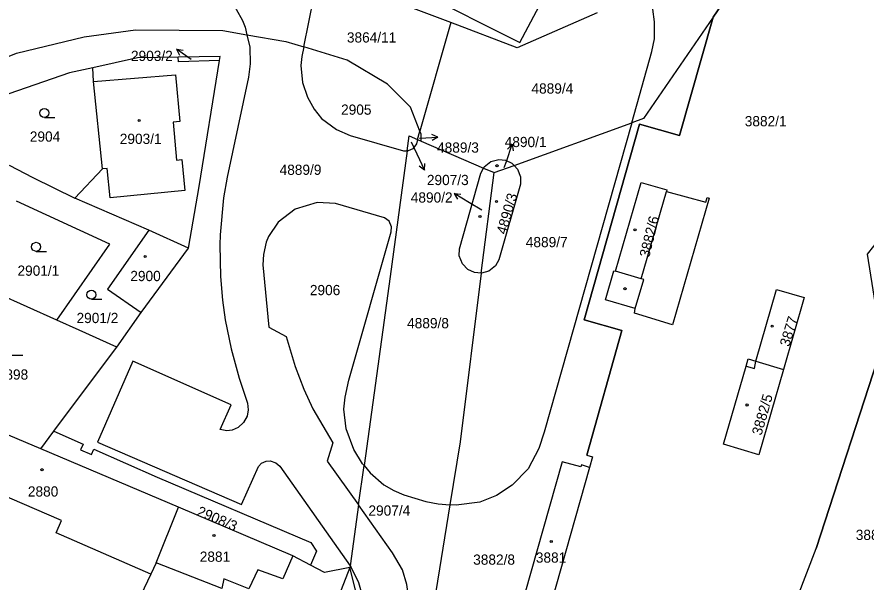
# Model space of a CAD drawing. Extents: x -527335 to -526256, y -1079142 to -1077836.
# Drawn here: x -526891.4 to -526750.1, y -1078714.2 to -1078620.2 of the extents above; entities that cross this region are included whole.
import ezdxf

# ---------------------------------------------------------------- set-up
doc = ezdxf.new("R2010")
doc.units = 0
for name, color, linetype in [('Hranice parcel', 7, 'Continuous'), ('Parcelní čísla', 7, 'Continuous'), ('Pop  PČ popisy', 7, 'Continuous'), ('Vnitřní kresba', 7, 'Continuous'), ('Vrstva 54', 7, 'Continuous'), ('Značky budov', 7, 'Continuous'), ('Značky kultur', 7, 'Continuous')]:
    doc.layers.add(name, color=color, linetype=linetype)

msp = doc.modelspace()

# ---------------------------------------------------------------- linework, layer by layer
at = {"layer": 'Hranice parcel'}
for p, q in [((-526843.73, -1078625.21), (-526841.41, -1078613.96)), ((-526819.27, -1078621.16), (-526824.4, -1078639.2)), ((-526808.76, -1078644.91), (-526789.19, -1078637.84)), ((-526824.79, -1078640.59), (-526824.4, -1078639.2)), ((-526824.79, -1078640.59), (-526824.19, -1078640.85)), ((-526824.19, -1078640.85), (-526813.82, -1078645.35)), ((-526813.82, -1078645.35), (-526812.08, -1078646.11)), ((-526812.08, -1078646.11), (-526808.76, -1078644.91)), ((-526814.2, -1078662.85), (-526812.08, -1078646.11)), ((-526869.47, -1078655.69), (-526881.81, -1078650.35)), ((-526862.92, -1078658.65), (-526869.47, -1078655.69)), ((-526870.77, -1078669.37), (-526862.92, -1078658.65)), ((-526884.81, -1078670.65), (-526900.22, -1078663.69)), ((-526874.82, -1078675.16), (-526870.77, -1078669.37)), ((-526768.55, -1078677.49), (-526763.94, -1078678.83)), ((-526887.47, -1078692.06), (-526885.27, -1078689.12)), ((-526864.56, -1078701.77), (-526887.47, -1078692.06)), ((-526834.61, -1078701.38), (-526833.7, -1078694.84)), ((-526796.21, -1078695.13), (-526804.6, -1078724.76)), ((-526868.26, -1078711.02), (-526864.56, -1078701.77)), ((-526845.53, -1078709.84), (-526864.56, -1078701.77)), ((-526834.61, -1078701.38), (-526836.01, -1078711.53)), ((-526819.43, -1078701.36), (-526822.95, -1078723.3)), ((-526842.59, -1078711.4), (-526845.53, -1078709.84)), ((-526836.05, -1078711.79), (-526839.19, -1078719.76)), ((-526836.01, -1078711.53), (-526836.05, -1078711.79)), ((-526833.99, -1078719.88), (-526836.05, -1078711.79))]:
    msp.add_line(p, q, dxfattribs=at)
for points in [[(-526766.12, -1078610.17), (-526769.16, -1078610.73), (-526775.66, -1078620.23)], [(-526869.37, -1078612.14), (-526867.13, -1078612.03), (-526863.95, -1078612.46), (-526860.92, -1078613.57), (-526858.13, -1078615.36), (-526857.06, -1078616.32), (-526854.94, -1078618.9), (-526853.89, -1078620.81), (-526853.48, -1078621.91), (-526853.17, -1078623.18)], [(-526789.19, -1078637.84), (-526785.84, -1078625.99), (-526785.42, -1078623.83), (-526785.41, -1078621.01), (-526785.67, -1078618.95), (-526786.3, -1078616.83), (-526788.13, -1078613.38), (-526789.05, -1078612.35)], [(-526819.27, -1078621.16), (-526833.71, -1078615.66), (-526841.41, -1078613.96)], [(-526824.79, -1078615.85), (-526807.79, -1078624.46), (-526803.66, -1078616.58)], [(-526794.91, -1078619.55), (-526808.25, -1078625.35), (-526819.27, -1078621.16)], [(-526775.66, -1078620.23), (-526781.26, -1078639.92), (-526787.88, -1078638.05), (-526797.07, -1078670.6), (-526790.82, -1078672.37), (-526796.68, -1078693.11), (-526795.72, -1078693.38), (-526796.21, -1078695.13)], [(-526775.66, -1078620.23), (-526787.22, -1078637.13), (-526789.19, -1078637.84)], [(-526921.59, -1078644.68), (-526904.95, -1078631.71), (-526891.51, -1078626.22), (-526880.24, -1078623.51), (-526871.73, -1078622.35), (-526857.21, -1078622.49), (-526853.17, -1078623.18)], [(-526853.17, -1078623.18), (-526852.68, -1078625.23), (-526852.63, -1078628.02), (-526852.92, -1078630.22), (-526856.44, -1078646.89), (-526857.06, -1078650.28), (-526857.65, -1078656.43), (-526857.7, -1078658.13), (-526857.58, -1078663.37), (-526857.25, -1078667.34), (-526856.78, -1078670.59), (-526855.82, -1078675.44), (-526854.48, -1078680.3), (-526853.09, -1078684.47), (-526852.97, -1078685.55), (-526853.14, -1078686.59), (-526853.72, -1078687.66), (-526854.66, -1078688.48), (-526855.62, -1078688.92), (-526856.53, -1078689.06), (-526857.64, -1078688.84), (-526855.82, -1078684.74), (-526872.17, -1078677.46), (-526878.01, -1078690.91), (-526854.06, -1078701.28), (-526851.27, -1078695), (-526850.77, -1078694.45), (-526849.95, -1078694.09), (-526849.31, -1078694.04), (-526848.37, -1078694.36), (-526847.72, -1078694.95), (-526836.01, -1078711.53)], [(-526853.17, -1078623.18), (-526846.72, -1078624.29), (-526843.73, -1078625.21)], [(-526843.73, -1078625.21), (-526844.05, -1078626.78), (-526844.2, -1078628.27), (-526843.91, -1078631.11), (-526843.13, -1078633.56), (-526842.02, -1078635.55), (-526840.76, -1078637.11), (-526838.3, -1078638.92), (-526836.02, -1078639.96), (-526827.16, -1078642.46), (-526826.53, -1078642.46)], [(-526824.4, -1078639.2), (-526825.96, -1078635.22), (-526829.78, -1078631.37), (-526836.5, -1078627.43), (-526843.73, -1078625.21)], [(-526864.61, -1078626.91), (-526871.37, -1078627.02), (-526878.81, -1078628.66)], [(-526857.75, -1078627.47), (-526857.64, -1078626.79), (-526864.61, -1078626.91)], [(-526857.75, -1078627.47), (-526864.55, -1078627.7), (-526864.61, -1078626.91)], [(-526878.81, -1078628.66), (-526882.67, -1078629.51), (-526901.46, -1078636.01), (-526901.58, -1078636.57)], [(-526881.81, -1078650.35), (-526877.21, -1078645.49), (-526878.67, -1078630.96), (-526878.81, -1078628.66)], [(-526862.92, -1078658.65), (-526861.14, -1078648.4), (-526857.75, -1078627.47)], [(-526789.19, -1078637.84), (-526803.74, -1078689.27), (-526804.63, -1078692.01), (-526806.42, -1078695.38), (-526809.08, -1078698.09), (-526811.68, -1078699.8), (-526814.45, -1078700.92), (-526818.39, -1078701.44), (-526819.43, -1078701.36)], [(-526826.53, -1078642.46), (-526826.2, -1078639.98), (-526824.79, -1078640.59)], [(-526824.19, -1078640.85), (-526824.2, -1078639.7), (-526824.4, -1078639.2)], [(-526824.79, -1078640.59), (-526825, -1078641.33), (-526825.59, -1078642.15), (-526826.34, -1078642.46), (-526826.53, -1078642.46)], [(-526826.53, -1078642.46), (-526829.34, -1078663.37), (-526833.7, -1078694.84)], [(-526813.82, -1078645.35), (-526813.7, -1078645.14), (-526812.63, -1078644.28), (-526811.27, -1078643.9), (-526810.18, -1078644.02), (-526809.12, -1078644.53), (-526808.76, -1078644.91)], [(-526892.72, -1078644.86), (-526888.78, -1078646.91), (-526881.81, -1078650.35)], [(-526814.2, -1078662.85), (-526815.36, -1078662.74), (-526816.43, -1078662.24), (-526817.34, -1078661.29), (-526817.86, -1078659.97), (-526817.84, -1078658.8), (-526814.29, -1078646.19), (-526813.82, -1078645.35)], [(-526808.76, -1078644.91), (-526808.17, -1078645.52), (-526807.69, -1078646.82), (-526807.7, -1078648.01), (-526811.28, -1078660.61), (-526811.85, -1078661.63), (-526812.94, -1078662.52), (-526814.17, -1078662.85), (-526814.2, -1078662.85)], [(-526788.7, -1078669.48), (-526788.59, -1078668.73), (-526793.57, -1078667.29), (-526792.14, -1078662.45), (-526791.9, -1078662.52), (-526787.63, -1078647.77), (-526783.36, -1078648.99), (-526783.43, -1078649.22), (-526776.87, -1078651.04), (-526776.62, -1078650.25), (-526776.3, -1078650.36), (-526782.4, -1078671.44), (-526788.7, -1078669.48)], [(-526884.81, -1078670.65), (-526875.97, -1078658.01), (-526891.48, -1078650.84)], [(-526833.7, -1078694.84), (-526833.97, -1078694.53), (-526835.42, -1078692.18), (-526836.66, -1078688.74), (-526837.04, -1078685.43), (-526836.83, -1078683.47), (-526836.21, -1078680.65), (-526829.17, -1078655.93), (-526829.11, -1078655.11), (-526829.53, -1078654.17), (-526830.32, -1078653.6), (-526838.47, -1078651.25), (-526841.47, -1078651.1), (-526845.15, -1078652.19), (-526847.97, -1078654.37), (-526849.57, -1078656.72), (-526849.98, -1078657.67), (-526850.44, -1078659.71), (-526850.52, -1078661.43), (-526849.51, -1078671.82), (-526846.64, -1078673.34), (-526845.17, -1078678.38), (-526843.73, -1078682.14), (-526842.22, -1078685.38), (-526838.87, -1078691.04), (-526839.82, -1078694.07), (-526834.61, -1078701.38)], [(-526869.47, -1078655.69), (-526876.34, -1078665.47), (-526870.77, -1078669.37)], [(-526814.2, -1078662.85), (-526817.74, -1078690.87), (-526819.43, -1078701.36)], [(-526768.55, -1078677.49), (-526765.14, -1078665.52), (-526760.53, -1078666.85), (-526763.94, -1078678.83)], [(-526874.82, -1078675.16), (-526881.1, -1078672.32), (-526884.81, -1078670.65)], [(-526885.27, -1078689.12), (-526880.66, -1078682.97), (-526874.82, -1078675.16)], [(-526766.02, -1078728.13), (-526758.54, -1078708.63), (-526747.6, -1078675.03)], [(-526763.94, -1078678.83), (-526768.04, -1078693.02), (-526773.94, -1078691.29), (-526770.16, -1078678.27), (-526769.81, -1078677.09), (-526768.55, -1078677.49)], [(-526887.47, -1078692.06), (-526904.29, -1078684.93), (-526904.54, -1078685.32), (-526910.1, -1078683.31)], [(-526885.27, -1078689.12), (-526880.41, -1078691.26), (-526880.83, -1078692.23), (-526879.04, -1078692.97), (-526878.66, -1078692.08), (-526868.1, -1078696.74), (-526842.55, -1078707.6), (-526841.58, -1078709.05), (-526842.59, -1078711.4)], [(-526833.7, -1078694.84), (-526832.67, -1078696.05), (-526830.4, -1078698.02), (-526828.77, -1078698.97), (-526827.06, -1078699.72), (-526823.43, -1078700.8), (-526821.39, -1078701.21), (-526819.43, -1078701.36)], [(-526796.21, -1078695.13), (-526797.53, -1078694.71), (-526797.63, -1078695.06), (-526800.78, -1078694.21), (-526809.06, -1078723.54), (-526804.6, -1078724.76)], [(-526822.95, -1078723.3), (-526827.09, -1078722.05), (-526826.54, -1078720.12), (-526826.24, -1078716.92), (-526826.57, -1078714.61), (-526827.31, -1078712.18), (-526828.95, -1078709.32), (-526834.61, -1078701.38)], [(-526845.53, -1078709.84), (-526847.23, -1078713.67), (-526851.39, -1078712.19), (-526852.86, -1078715.34), (-526856.99, -1078713.69), (-526857.33, -1078715.27), (-526868.26, -1078711.02)], [(-526868.26, -1078711.02), (-526869.17, -1078712.87), (-526874.21, -1078723.48)], [(-526836.05, -1078711.79), (-526840.28, -1078712.62), (-526842.59, -1078711.4)], [(-526836.01, -1078711.53), (-526835.83, -1078711.79), (-526834.6, -1078714.3), (-526833.95, -1078716.6), (-526833.92, -1078719.44)]]:
    msp.add_lwpolyline(points, dxfattribs=at)
at = {"layer": 'Pop  PČ popisy'}
for p, q in [((-526862.45, -1078627.3), (-526864.91, -1078625.58)), ((-526864.91, -1078625.58), (-526863.8, -1078625.74)), ((-526864.91, -1078625.58), (-526864.38, -1078626.56)), ((-526821.41, -1078640.19), (-526822.44, -1078639.76)), ((-526825.84, -1078640.96), (-526824.9, -1078642.99)), ((-526824.46, -1078640.41), (-526824.4, -1078640.4)), ((-526824.4, -1078640.4), (-526821.41, -1078640.19)), ((-526821.41, -1078640.19), (-526822.37, -1078640.76)), ((-526810.04, -1078644.24), (-526809.06, -1078641.4)), ((-526809.06, -1078641.4), (-526809.86, -1078642.19)), ((-526809.06, -1078641.4), (-526808.92, -1078642.51)), ((-526824.9, -1078642.99), (-526823.63, -1078645.71)), ((-526810.38, -1078645.23), (-526810.04, -1078644.24)), ((-526823.63, -1078645.71), (-526824.51, -1078645.01)), ((-526823.63, -1078645.71), (-526823.6, -1078644.59)), ((-526816.17, -1078651.13), (-526818.74, -1078649.58)), ((-526818.74, -1078649.58), (-526817.63, -1078649.67)), ((-526818.74, -1078649.58), (-526818.14, -1078650.53)), ((-526814.14, -1078652.37), (-526816.17, -1078651.13))]:
    msp.add_line(p, q, dxfattribs=at)
at = {"layer": 'Vnitřní kresba'}
for p, q in [((-526878.67, -1078630.96), (-526865.05, -1078629.86)), ((-526865.05, -1078629.86), (-526864.34, -1078637.6)), ((-526864.34, -1078637.6), (-526865.46, -1078637.7)), ((-526865.46, -1078637.7), (-526864.89, -1078644.02)), ((-526864.89, -1078644.02), (-526863.99, -1078643.94)), ((-526863.99, -1078643.94), (-526863.53, -1078649.08)), ((-526876.39, -1078645.4), (-526877.21, -1078645.49)), ((-526875.9, -1078650.32), (-526876.39, -1078645.4)), ((-526863.53, -1078649.08), (-526875.9, -1078650.32)), ((-526787.62, -1078663.77), (-526783.43, -1078649.22)), ((-526787.62, -1078663.77), (-526791.9, -1078662.52)), ((-526788.59, -1078668.73), (-526787.18, -1078663.9)), ((-526787.18, -1078663.9), (-526787.62, -1078663.77)), ((-526770.16, -1078678.27), (-526768.76, -1078678.67)), ((-526768.76, -1078678.67), (-526768.55, -1078677.49)), ((-526884.03, -1078703.98), (-526913.74, -1078691.1)), ((-526884.91, -1078706.03), (-526884.03, -1078703.98)), ((-526869.17, -1078712.87), (-526884.91, -1078706.03))]:
    msp.add_line(p, q, dxfattribs=at)
at = {"layer": 'Vrstva 54'}
for points in [[(-526796.68, -1078693.11), (-526790.82, -1078672.37), (-526797.07, -1078670.6), (-526787.88, -1078638.05), (-526781.26, -1078639.92), (-526775.66, -1078620.23), (-526769.16, -1078610.73), (-526766.12, -1078610.17)], [(-526747.97, -1078618.86), (-526745.47, -1078625.12), (-526744.86, -1078629.16), (-526744.86, -1078637), (-526748.33, -1078652.79), (-526747.95, -1078657.02), (-526750.05, -1078659.68), (-526747.6, -1078675.03), (-526758.54, -1078708.63)]]:
    msp.add_lwpolyline(points, dxfattribs=at)
at = {"layer": 'Značky budov'}
for centre in [(-526871.11, -1078637.45), (-526811.59, -1078644.96), (-526811.69, -1078650.91), (-526814.42, -1078653.41), (-526788.64, -1078655.61), (-526870.09, -1078660.07), (-526790.31, -1078665.42), (-526765.83, -1078671.65), (-526770.01, -1078684.75), (-526887.25, -1078695.52), (-526858.66, -1078706.46), (-526802.57, -1078707.45)]:
    msp.add_circle(centre, 0.175, dxfattribs=at)
at = {"layer": 'Značky kultur'}
for p, q in [((-526886.86, -1078636.93), (-526885.11, -1078636.93)), ((-526888.23, -1078659.2), (-526886.48, -1078659.2)), ((-526879.03, -1078667.16), (-526877.28, -1078667.16)), ((-526892.21, -1078676.49), (-526890.46, -1078676.49))]:
    msp.add_line(p, q, dxfattribs=at)
for centre in [(-526886.86, -1078636.18), (-526888.23, -1078658.45), (-526879.03, -1078666.41)]:
    msp.add_circle(centre, 0.75, dxfattribs=at)

# ---------------------------------------------------------------- texts
at = {"layer": 'Parcelní čísla'}
for s, p in [('3864/11', (-526836.55, -1078624.47)), ('2903/2', (-526872.46, -1078627.54)), ('4889/4', (-526805.86, -1078632.96)), ('2905', (-526837.52, -1078636.48)), ('3882/1', (-526770.39, -1078638.4)), ('2904', (-526889.28, -1078640.96)), ('2903/1', (-526874.32, -1078641.34)), ('4890/1', (-526810.31, -1078641.86)), ('4889/3', (-526821.56, -1078642.79)), ('4889/9', (-526847.74, -1078646.48)), ('2907/3', (-526823.25, -1078648.18)), ('4890/2', (-526825.93, -1078651.09)), ('4889/7', (-526806.8, -1078658.51)), ('2901/1', (-526891.33, -1078663.26)), ('2900', (-526872.57, -1078664.15)), ('2906', (-526842.71, -1078666.49)), ('2901/2', (-526881.51, -1078671.13)), ('4889/8', (-526826.54, -1078671.99)), ('2898', (-526894.61, -1078680.54)), ('2880', (-526889.6, -1078699.98)), ('2907/4', (-526832.97, -1078703.16)), ('3882/7', (-526751.93, -1078707.2)), ('2881', (-526861.02, -1078710.83)), ('3881', (-526805.13, -1078710.98)), ('3882/8', (-526815.55, -1078711.32))]:
    msp.add_text(s, height=1.7, dxfattribs=at).set_placement(p)
for s, rotation, p in [('4890/3', 74, (-526810.09, -1078656.5)), ('3882/6', 76, (-526786.29, -1078660.33)), ('3877', 73, (-526763, -1078675.17)), ('3882/5', 74, (-526767.62, -1078689.92)), ('2908/3', 337, (-526861.64, -1078703.07))]:
    msp.add_text(s, height=1.7, rotation=rotation, dxfattribs=at).set_placement(p)

doc.saveas('drawing.dxf')
